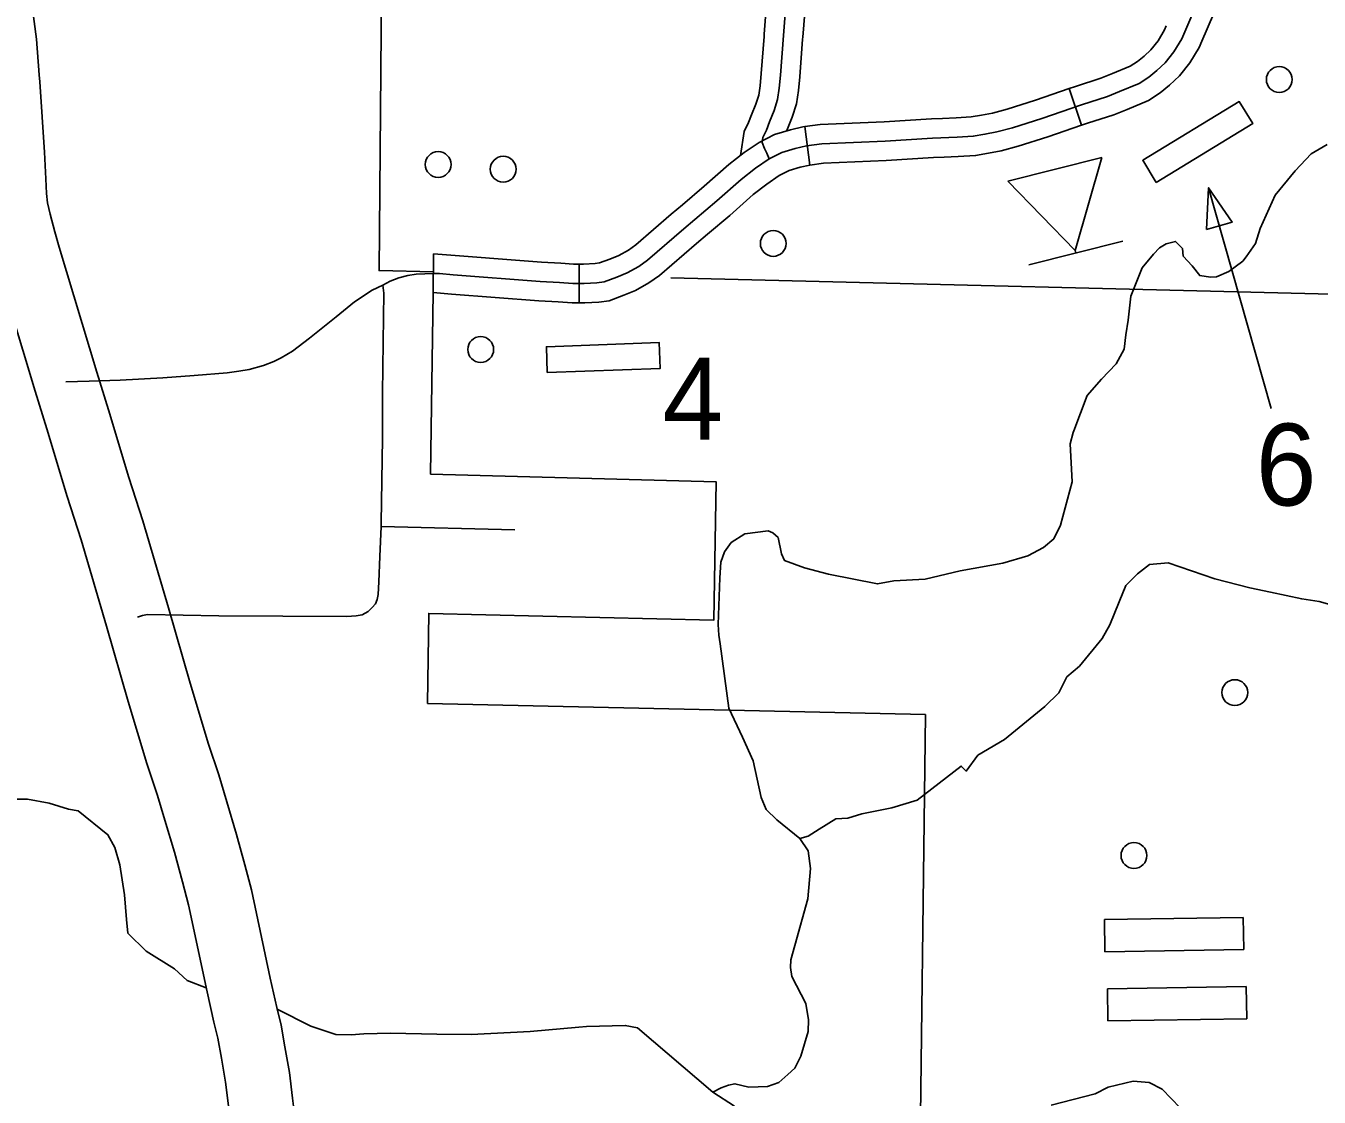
# Model space of a CAD drawing. Extents: x 1382482 to 1385815, y 1168351 to 1170484.
# Drawn here: x 1384488.7 to 1384689, y 1169143.7 to 1169309.6 of the extents above; entities that cross this region are included whole.
import ezdxf

# ---------------------------------------------------------------- set-up
doc = ezdxf.new("R2010")
doc.units = 0
for name, color, linetype in [('10', 7, 'Continuous'), ('35', 7, 'Continuous'), ('45', 7, 'Continuous'), ('5', 7, 'Continuous'), ('57', 7, 'Continuous'), ('6', 7, 'Continuous'), ('Default', 7, 'Continuous')]:
    doc.layers.add(name, color=color, linetype=linetype)

msp = doc.modelspace()

# ---------------------------------------------------------------- linework, layer by layer
at = {"layer": '10'}
for points in [[(1384489.59, 1169313.88), (1384490.38, 1169307.55), (1384490.82, 1169302.03), (1384490.9, 1169300.98), (1384491.64, 1169290.08), (1384491.84, 1169285.92), (1384491.93, 1169283.67), (1384492.11, 1169282.21), (1384492.51, 1169280.45), (1384493.25, 1169277.75), (1384493.88, 1169275.34), (1384499.74, 1169256), (1384501.55, 1169250.18), (1384504.71, 1169239.7), (1384506.87, 1169232.97), (1384510.85, 1169219.48), (1384514.2, 1169207.82), (1384517.01, 1169198.41), (1384518.61, 1169193.65)], [(1384509.13, 1169190.46), (1384507.47, 1169195.39), (1384504.6, 1169205.01), (1384501.25, 1169216.69), (1384497.32, 1169230.02), (1384495.16, 1169236.73), (1384491.99, 1169247.25), (1384490.18, 1169253.06), (1384484.26, 1169272.62), (1384483.6, 1169275.15), (1384482.81, 1169278.01), (1384482.25, 1169280.48), (1384481.95, 1169282.86), (1384481.85, 1169285.5), (1384481.66, 1169289.5), (1384480.92, 1169300.27), (1384480.85, 1169301.27), (1384480.43, 1169306.53), (1384479.68, 1169312.48)], [(1384518.61, 1169193.65), (1384519.86, 1169189.45), (1384521.36, 1169184.42), (1384522.68, 1169179.68), (1384523.68, 1169175.81), (1384526.58, 1169162.13)], [(1384516.8, 1169160.05), (1384513.94, 1169173.52), (1384513.02, 1169177.09), (1384511.75, 1169181.65), (1384510.28, 1169186.6), (1384509.13, 1169190.46)], [(1384526.58, 1169162.13), (1384527.61, 1169157.62), (1384528.26, 1169154.89), (1384528.87, 1169151.52), (1384529.56, 1169147.56), (1384530.06, 1169143.59), (1384530.46, 1169140.27), (1384530.72, 1169135.7), (1384530.75, 1169128.28), (1384530.76, 1169118.44), (1384530.93, 1169110.92), (1384530.91, 1169104.17), (1384531.04, 1169098.92), (1384530.92, 1169092.95), (1384531.06, 1169090.6), (1384531.05, 1169086.99), (1384531.01, 1169081.11), (1384531.18, 1169078.43), (1384531.55, 1169075.06), (1384531.97, 1169071.58)], [(1384520.13, 1169142.36), (1384519.67, 1169146.07), (1384519.02, 1169149.78), (1384518.47, 1169152.85), (1384517.87, 1169155.34), (1384516.8, 1169160.05)]]:
    msp.add_lwpolyline(points, dxfattribs=at)
at = {"layer": '35'}
for points in [[(1384690.28, 1169291.25), (1384687.78, 1169289.83), (1384685.33, 1169287.2), (1384682.21, 1169283.42), (1384679.89, 1169278.27), (1384679.16, 1169275.95), (1384677.71, 1169273.88), (1384677.2, 1169273.2), (1384675.02, 1169271.59), (1384673.11, 1169270.77), (1384672.19, 1169270.73), (1384670.53, 1169270.95), (1384669.37, 1169272.47), (1384667.99, 1169273.99)], [(1384667.99, 1169273.99), (1384667.85, 1169275.15), (1384666.76, 1169276.24), (1384665.31, 1169275.88), (1384664.3, 1169275.24), (1384663.35, 1169274.28), (1384661.61, 1169272.18), (1384659.87, 1169267.75), (1384659.43, 1169264.05), (1384659.09, 1169261.8), (1384658.83, 1169259.56), (1384657.57, 1169257.31), (1384655.3, 1169254.91), (1384653.12, 1169252.37), (1384651.02, 1169246.93)], [(1384651.02, 1169246.93), (1384650.91, 1169246.64), (1384650.48, 1169244.92), (1384650.79, 1169239.03), (1384648.99, 1169232.3), (1384647.93, 1169230.17), (1384646.35, 1169228.84), (1384643.92, 1169227.55), (1384640.06, 1169226.44), (1384633.41, 1169225.23), (1384628, 1169223.96), (1384623.18, 1169223.68), (1384620.65, 1169223.2), (1384613.06, 1169224.71), (1384609.31, 1169225.69), (1384606.21, 1169226.84), (1384605.79, 1169227.87), (1384605.24, 1169230.39), (1384604.43, 1169231.1), (1384603.72, 1169231.41), (1384600.09, 1169230.94), (1384597.96, 1169229.6), (1384596.93, 1169228.18), (1384596.36, 1169226.6), (1384596.24, 1169224.16), (1384595.96, 1169216.94), (1384596.07, 1169215.26), (1384596.28, 1169213.94), (1384597.59, 1169203.95), (1384599.73, 1169199.49), (1384601.39, 1169195.82), (1384602.62, 1169190.11), (1384603.39, 1169188.28), (1384605.04, 1169186.68), (1384608.59, 1169183.8), (1384609.89, 1169181.87), (1384610.24, 1169179.15), (1384609.83, 1169174.43), (1384607.81, 1169167.22), (1384607.22, 1169164.99), (1384607.15, 1169163.78), (1384607.34, 1169162.39), (1384609.51, 1169158.25), (1384609.95, 1169155.72), (1384609.87, 1169153.91), (1384608.77, 1169150.05), (1384607.82, 1169148.19), (1384606.75, 1169147.21), (1384605.33, 1169146.02), (1384603.59, 1169145.39)], [(1384695, 1169218.79), (1384689.01, 1169220.51), (1384686.34, 1169220.89), (1384681.47, 1169221.93), (1384678.3, 1169222.59), (1384672.86, 1169224.01), (1384665.63, 1169226.47), (1384662.76, 1169226.23), (1384660.87, 1169224.75), (1384659.08, 1169222.97), (1384658.08, 1169220.41), (1384656.59, 1169216.88), (1384655.4, 1169214.75), (1384651.92, 1169210.49), (1384649.94, 1169208.8), (1384648.71, 1169206.35), (1384646.54, 1169204.22), (1384640.3, 1169199.1), (1384636.18, 1169196.69), (1384634.37, 1169194.22), (1384633.59, 1169194.99), (1384626.79, 1169189.71), (1384622.85, 1169188.54), (1384618.21, 1169187.6), (1384616.02, 1169186.94), (1384614.17, 1169186.84), (1384611.58, 1169185.23), (1384609.91, 1169184.15), (1384608.59, 1169183.8)], [(1384486.6, 1169189.87), (1384489.02, 1169189.87), (1384492.37, 1169189.26), (1384495.33, 1169188.32), (1384496.85, 1169188.05), (1384501.46, 1169184.36), (1384502.54, 1169182.41), (1384503.3, 1169179.69), (1384504.01, 1169175.04), (1384504.31, 1169171.23), (1384504.56, 1169169.13), (1384507.4, 1169166.33), (1384511.78, 1169163.6), (1384513.73, 1169161.79), (1384516.67, 1169160.66)], [(1384527.67, 1169157.37), (1384532.87, 1169154.7), (1384536.73, 1169153.41), (1384539.13, 1169153.36), (1384541.09, 1169153.53), (1384545.19, 1169153.65), (1384552.37, 1169153.49)], [(1384552.37, 1169153.49), (1384557.7, 1169153.42), (1384566.85, 1169153.89), (1384574.39, 1169154.57), (1384575.57, 1169154.68), (1384581.57, 1169154.84), (1384583.46, 1169154.44), (1384595.14, 1169144.5), (1384598.5, 1169142.35)], [(1384603.59, 1169145.39), (1384600.73, 1169145.26), (1384598.55, 1169145.79), (1384597.56, 1169145.59), (1384596.42, 1169145.16), (1384595.14, 1169144.5)], [(1384647.5, 1169142.49), (1384654.33, 1169144.26), (1384656.33, 1169145.26), (1384660.21, 1169146.2), (1384662.69, 1169146.01), (1384664.73, 1169144.94), (1384667.49, 1169142.09)]]:
    msp.add_lwpolyline(points, dxfattribs=at)
at = {"layer": '45'}
for points in [[(1384610.14, 1169371.02), (1384609.13, 1169356.96), (1384608.36, 1169343.82), (1384607.52, 1169328.74), (1384606.92, 1169318.92), (1384606.08, 1169308.13), (1384605.63, 1169302.01), (1384605.42, 1169299.98), (1384605.17, 1169298.24), (1384604.62, 1169296.5), (1384603.9, 1169294.76), (1384603.43, 1169293.49), (1384602.88, 1169292.35), (1384602.75, 1169291.55), (1384603.13, 1169290.66), (1384603.51, 1169289.94), (1384603.86, 1169289.02)], [(1384604.53, 1169329.03), (1384604.52, 1169328.92), (1384603.93, 1169319.12), (1384603.09, 1169308.36), (1384603.06, 1169308.01)], [(1384610.52, 1169328.69), (1384610.51, 1169328.57), (1384609.92, 1169318.71), (1384609.07, 1169307.9), (1384609.04, 1169307.58)], [(1384603.06, 1169308.01), (1384602.64, 1169302.27), (1384602.44, 1169300.35), (1384602.23, 1169298.91), (1384601.79, 1169297.53), (1384601.1, 1169295.86), (1384600.66, 1169294.66), (1384599.98, 1169293.25), (1384599.4, 1169289.55)], [(1384609.04, 1169307.58), (1384608.62, 1169301.74), (1384608.4, 1169299.6), (1384608.1, 1169297.56), (1384607.44, 1169295.47), (1384606.59, 1169293.43)]]:
    msp.add_lwpolyline(points, dxfattribs=at)
at = {"layer": '5'}
msp.add_lwpolyline([(1384701.43, 1169267.8), (1384588.62, 1169270.62)], dxfattribs=at)
at = {"layer": '57'}
for p, q in [((1384655.35, 1169289.25), (1384640.81, 1169285.58)), ((1384651.26, 1169274.82), (1384655.35, 1169289.25)), ((1384640.81, 1169285.58), (1384651.26, 1169274.82)), ((1384658.63, 1169276.27), (1384644.09, 1169272.6)), ((1384651.26, 1169274.82), (1384651.36, 1169274.43)), ((1384677.28, 1169171.57), (1384655.78, 1169171.25)), ((1384655.78, 1169171.25), (1384655.86, 1169166.25)), ((1384677.36, 1169166.57), (1384677.28, 1169171.57)), ((1384655.86, 1169166.25), (1384677.36, 1169166.57)), ((1384677.74, 1169160.85), (1384656.24, 1169160.52)), ((1384656.24, 1169160.52), (1384656.32, 1169155.52)), ((1384677.81, 1169155.85), (1384677.74, 1169160.85)), ((1384656.32, 1169155.52), (1384677.81, 1169155.85))]:
    msp.add_line(p, q, dxfattribs=at)
at = {"layer": '6'}
for points in [[(1384544.93, 1169450.44), (1384544.32, 1169376.84), (1384543.45, 1169271.74), (1384551.85, 1169271.53)], [(1384551.81, 1169268.36), (1384551.43, 1169240.21), (1384595.64, 1169239.04), (1384595.31, 1169217.6), (1384551.14, 1169218.65), (1384550.96, 1169204.7), (1384628.04, 1169202.97), (1384627.06, 1169124.2)]]:
    msp.add_lwpolyline(points, dxfattribs=at)
at = {"layer": 'Default'}
for p, q in [((1384650.3, 1169299.92), (1384652.24, 1169294.25)), ((1384610.14, 1169288.08), (1384609.36, 1169294.03)), ((1384610.14, 1169288.08), (1384610.14, 1169288.08)), ((1384574.42, 1169272.73), (1384574.42, 1169266.73))]:
    msp.add_line(p, q, dxfattribs=at)
for points in [[(1384678.9, 1169326.23), (1384678.69, 1169325.91), (1384677.9, 1169324.62), (1384676.54, 1169321.36), (1384674.63, 1169316.05), (1384670.86, 1169307.27)], [(1384671.83, 1169317.15), (1384667.76, 1169307.64), (1384666.54, 1169305.62), (1384665.18, 1169303.9), (1384663.89, 1169302.7), (1384662.65, 1169301.68), (1384661.17, 1169300.71), (1384658.13, 1169299.47), (1384656.23, 1169298.69), (1384652.21, 1169297.4), (1384646.06, 1169295.3), (1384641.55, 1169293.86), (1384639.09, 1169293.2), (1384637.27, 1169292.85), (1384635.47, 1169292.54), (1384632.95, 1169292.38), (1384629.13, 1169292.23), (1384621.82, 1169291.8), (1384611.99, 1169291.35), (1384609.62, 1169291.04), (1384607.9, 1169290.65), (1384605.8, 1169290.03), (1384603.86, 1169289.02), (1384601.76, 1169287.57), (1384599.5, 1169285.86), (1384595.77, 1169282.55), (1384590.63, 1169278.19), (1384585.03, 1169273.33), (1384583.65, 1169272.37), (1384581.86, 1169271.36), (1384580.26, 1169270.73), (1384578.32, 1169270), (1384577.19, 1169269.84), (1384575.2, 1169269.73), (1384573.45, 1169269.73), (1384571.39, 1169269.88), (1384568.39, 1169270.04), (1384554.92, 1169271.09), (1384552.78, 1169271.28), (1384551.85, 1169271.28)], [(1384665.35, 1169309.63), (1384665.08, 1169309.01), (1384664.07, 1169307.33), (1384662.97, 1169305.94), (1384661.92, 1169304.96), (1384660.87, 1169304.11), (1384659.76, 1169303.38), (1384657, 1169302.24), (1384655.2, 1169301.51), (1384651.27, 1169300.25), (1384650.3, 1169299.92)], [(1384670.86, 1169307.27), (1384670.43, 1169306.27), (1384669.01, 1169303.9), (1384667.39, 1169301.87), (1384665.87, 1169300.44), (1384664.42, 1169299.26), (1384662.58, 1169298.05), (1384659.27, 1169296.69), (1384657.25, 1169295.87), (1384653.15, 1169294.56), (1384652.24, 1169294.25)], [(1384630.7, 1169295.29), (1384632.79, 1169295.38), (1384635.12, 1169295.52), (1384636.73, 1169295.8), (1384638.42, 1169296.13), (1384640.7, 1169296.74), (1384645.12, 1169298.15), (1384650.3, 1169299.92)], [(1384609.36, 1169294.03), (1384611.73, 1169294.34), (1384621.66, 1169294.79), (1384628.98, 1169295.22), (1384630.7, 1169295.29)], [(1384609.36, 1169294.03), (1384609.09, 1169294), (1384607.14, 1169293.55), (1384604.67, 1169292.82), (1384602.31, 1169291.59), (1384600, 1169290.01), (1384597.59, 1169288.18), (1384593.8, 1169284.82), (1384590.42, 1169281.94)], [(1384652.24, 1169294.25), (1384647, 1169292.45), (1384642.39, 1169290.98), (1384639.77, 1169290.27), (1384637.8, 1169289.9), (1384635.83, 1169289.55), (1384633.1, 1169289.39), (1384630.95, 1169289.3)], [(1384630.95, 1169289.3), (1384629.28, 1169289.23), (1384621.97, 1169288.8), (1384612.25, 1169288.36), (1384610.14, 1169288.08)], [(1384610.14, 1169288.08), (1384608.66, 1169287.75), (1384606.93, 1169287.23), (1384605.4, 1169286.44), (1384603.51, 1169285.14), (1384601.4, 1169283.54), (1384597.74, 1169280.29), (1384594.3, 1169277.37)], [(1384681.62, 1169250.37), (1384671.89, 1169284.55)], [(1384590.42, 1169281.94), (1384588.68, 1169280.47), (1384583.19, 1169275.7), (1384582.06, 1169274.92), (1384580.56, 1169274.07), (1384579.18, 1169273.52), (1384577.58, 1169272.93), (1384576.9, 1169272.83), (1384575.12, 1169272.73), (1384574.42, 1169272.73)], [(1384594.3, 1169277.37), (1384592.59, 1169275.92), (1384586.87, 1169270.95), (1384585.24, 1169269.83), (1384583.16, 1169268.65), (1384581.34, 1169267.93), (1384579.06, 1169267.07), (1384577.48, 1169266.86), (1384575.29, 1169266.73), (1384574.42, 1169266.73)], [(1384574.42, 1169266.73), (1384573.34, 1169266.73), (1384571.2, 1169266.89), (1384568.2, 1169267.04), (1384554.67, 1169268.1), (1384551.81, 1169268.36), (1384551.89, 1169274.34)], [(1384551.89, 1169274.34), (1384568.59, 1169273.03), (1384571.58, 1169272.88), (1384573.57, 1169272.73), (1384574.42, 1169272.73)], [(1384551.85, 1169271.28), (1384549.21, 1169271.19), (1384547.92, 1169270.96), (1384546.52, 1169270.59), (1384545.18, 1169270.08), (1384544.01, 1169269.48), (1384542.39, 1169268.68), (1384539.66, 1169266.92), (1384536.78, 1169264.55), (1384532.65, 1169261.26), (1384530.05, 1169259.26), (1384528.29, 1169258.24), (1384527.13, 1169257.64), (1384525.55, 1169257.04), (1384523.33, 1169256.39), (1384521.75, 1169256.17), (1384519.94, 1169255.92), (1384514.82, 1169255.51), (1384509.95, 1169255.13), (1384503.36, 1169254.76), (1384498.53, 1169254.62), (1384494.96, 1169254.53)], [(1384506.05, 1169218.08), (1384506.83, 1169218.3), (1384507.58, 1169218.46), (1384518.65, 1169218.27), (1384538.47, 1169218.16), (1384539.9, 1169218.27), (1384540.84, 1169218.41), (1384541.75, 1169218.94), (1384542.35, 1169219.56), (1384542.88, 1169220.13), (1384543.13, 1169220.77), (1384543.29, 1169221.58), (1384543.39, 1169223.54), (1384543.58, 1169227.44), (1384543.77, 1169232.11), (1384543.76, 1169232.69), (1384543.96, 1169245.73), (1384543.96, 1169252.75), (1384544.15, 1169264.51), (1384544.2, 1169268.22), (1384544.01, 1169269.48)], [(1384543.77, 1169232.11), (1384564.45, 1169231.58)]]:
    msp.add_lwpolyline(points, dxfattribs=at)
for points in [[(1384663.78, 1169285.4), (1384661.71, 1169288.82), (1384676.66, 1169297.91), (1384678.74, 1169294.49)], [(1384671.6, 1169278.11), (1384675.53, 1169279.22), (1384671.89, 1169284.55)], [(1384569.49, 1169255.95), (1384569.35, 1169259.95), (1384586.83, 1169260.59), (1384586.98, 1169256.59)]]:
    msp.add_lwpolyline(points, close=True, dxfattribs=at)
for centre in [(1384682.85, 1169301.32), (1384552.59, 1169288.16), (1384562.67, 1169287.43), (1384604.49, 1169275.94), (1384559.18, 1169259.51), (1384675.96, 1169206.38), (1384660.35, 1169181.15)]:
    msp.add_circle(centre, 2, dxfattribs=at)

# ---------------------------------------------------------------- texts
for s, p in [('4', (1384587.31, 1169245.56)), ('6', (1384679.2, 1169235.36))]:
    msp.add_text(s, height=12.67, dxfattribs=at).set_placement(p)

doc.saveas('drawing.dxf')
